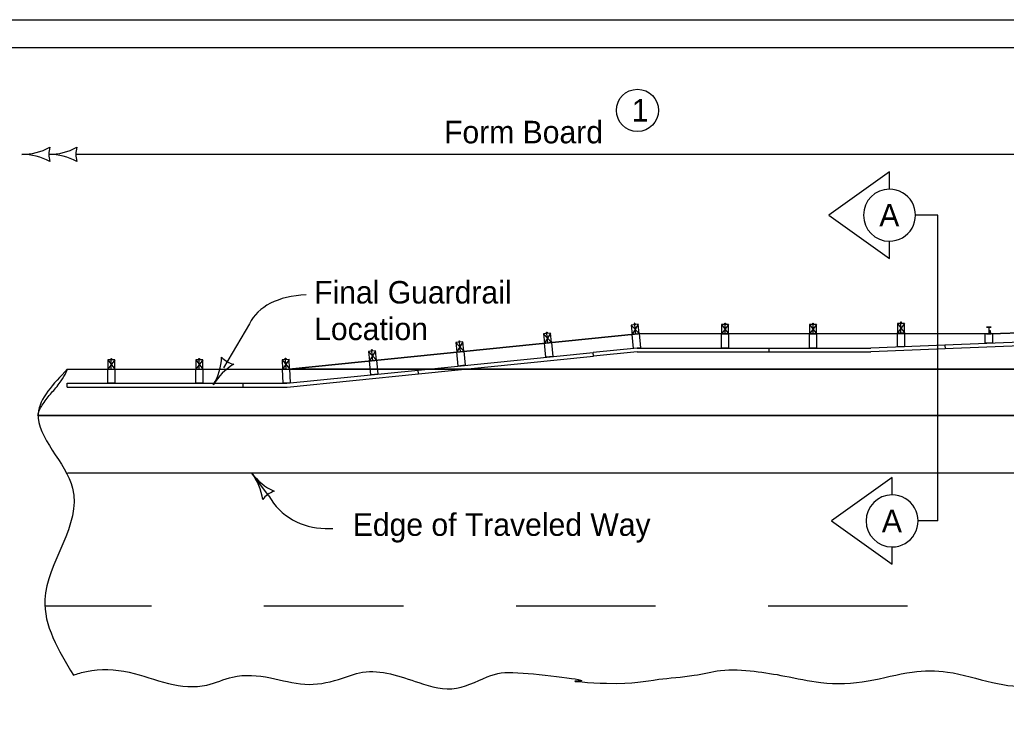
# Model space of a CAD drawing. Extents: x 8045 to 81668, y 6217 to 16762.
# Drawn here: x 10335 to 11036, y 9440 to 9944 of the extents above; entities that cross this region are included whole.
import ezdxf

# ---------------------------------------------------------------- set-up
doc = ezdxf.new("R2010")
doc.units = 0
for name, color, linetype in [('dsnCellElements', 7, 'Continuous'), ('dsnStdDetailExtension', 7, 'Continuous'), ('dsnStdDimension', 7, 'Continuous'), ('dsnStdLabel', 7, 'Continuous'), ('dsnStdNote', 7, 'Continuous'), ('dsnStdPattern', 7, 'Continuous'), ('dsnStdSection', 7, 'Continuous'), ('Level 4', 7, 'Continuous'), ('Level 8', 7, 'Continuous')]:
    doc.layers.add(name, color=color, linetype=linetype)

msp = doc.modelspace()

# ---------------------------------------------------------------- linework, layer by layer
at = {"layer": 'dsnCellElements'}
msp.add_line((10375.45, 9848.49), (11397.86, 9848.49), dxfattribs=at)
msp.add_line((10375.45, 9848.49), (11397.86, 9848.49), dxfattribs=at)
for centre, radius, start, end in [((10336.23, 9890.84), 42.5, 270, 298.07249), ((10336.23, 9890.84), 42.5, 270, 298.07249), ((10355.45, 9890.84), 42.5, 270, 298.07249), ((10371.87, 9848.34), 16.42, 162.26665, 197.73335), ((10355.45, 9890.84), 42.5, 270, 298.07249), ((10371.87, 9848.34), 16.42, 162.26665, 197.73335), ((10391.09, 9848.34), 16.42, 162.26665, 197.73335), ((10391.09, 9848.34), 16.42, 162.26665, 197.73335), ((10336.23, 9805.84), 42.5, 61.92751, 90), ((10336.23, 9805.84), 42.5, 61.92751, 90), ((10355.45, 9805.84), 42.5, 61.92751, 90), ((10355.45, 9805.84), 42.5, 61.92751, 90)]:
    msp.add_arc(centre, radius, start, end, dxfattribs=at)
at = {"layer": 'dsnStdDetailExtension'}
for p, q in [((10769.49, 9727.04), (10775.13, 9720.91)), ((10774.47, 9727.54), (10770.15, 9720.41)), ((10771.88, 9728.26), (10771.87, 9728.33)), ((10772.64, 9720.66), (10771.98, 9727.29)), ((10833.64, 9727.37), (10838.64, 9720.71)), ((10838.64, 9727.37), (10833.64, 9720.71)), ((10836.14, 9728.35), (10836.14, 9728.42)), ((10836.14, 9720.71), (10836.14, 9727.37)), ((10896.14, 9727.37), (10901.14, 9720.71)), ((10901.14, 9727.37), (10896.14, 9720.71)), ((10898.64, 9728.35), (10898.64, 9728.42)), ((10898.64, 9720.71), (10898.64, 9727.37)), ((10958.64, 9728.24), (10963.64, 9721.57)), ((10963.64, 9728.24), (10958.64, 9721.57)), ((10961.14, 9729.21), (10961.14, 9729.28)), ((10961.14, 9721.57), (10961.14, 9728.24)), ((10707.03, 9720.76), (10712.67, 9714.63)), ((10712, 9721.26), (10707.69, 9714.13)), ((10709.42, 9721.98), (10709.41, 9722.05)), ((10710.18, 9714.38), (10709.51, 9721.01)), ((10770.15, 9720.41), (10775.13, 9720.91)), ((10772.64, 9720.66), (10770.15, 9720.41)), ((10772.64, 9720.66), (10770.15, 9720.41)), ((10771.15, 9710.45), (10770.15, 9720.41)), ((10775.13, 9720.91), (10776.13, 9710.95)), ((10833.64, 9720.71), (10838.64, 9720.71)), ((10833.64, 9710.7), (10833.64, 9720.71)), ((10838.64, 9720.71), (10838.64, 9710.7)), ((10896.14, 9720.71), (10901.14, 9720.71)), ((10896.14, 9710.7), (10896.14, 9720.71)), ((10901.14, 9720.71), (10901.14, 9710.7)), ((10958.64, 9721.57), (10963.64, 9721.57)), ((10958.64, 9711.56), (10958.64, 9721.57)), ((10963.64, 9721.57), (10963.64, 9711.56)), ((10644.84, 9714.51), (10650.48, 9708.38)), ((10649.81, 9715.01), (10645.51, 9707.88)), ((10647.23, 9715.73), (10647.22, 9715.8)), ((10647.99, 9708.13), (10647.33, 9714.76)), ((10707.69, 9714.13), (10712.67, 9714.63)), ((10708.69, 9704.17), (10707.69, 9714.13)), ((10712.67, 9714.63), (10713.67, 9704.67)), ((10963.64, 9711.56), (10958.64, 9711.56)), ((10582.66, 9708.3), (10588.3, 9702.13)), ((10587.64, 9708.8), (10583.33, 9701.63)), ((10585.05, 9709.52), (10585.05, 9709.59)), ((10585.81, 9701.88), (10585.15, 9708.55)), ((10617.9, 9695.05), (10742.28, 9707.55)), ((10618.17, 9692.35), (10742.55, 9704.85)), ((10645.51, 9707.88), (10650.49, 9708.38)), ((10646.51, 9697.92), (10645.51, 9707.88)), ((10650.49, 9708.38), (10651.49, 9698.42)), ((10713.67, 9704.67), (10708.69, 9704.17)), ((10773.64, 9710.7), (10742.28, 9707.55)), ((10742.55, 9704.85), (10742.28, 9707.55)), ((10742.55, 9704.87), (10742.28, 9707.55)), ((10773.64, 9707.99), (10742.55, 9704.87)), ((10776.13, 9710.95), (10771.15, 9710.45)), ((10773.64, 9710.7), (10867.39, 9710.7)), ((10773.64, 9707.99), (10867.39, 9707.99)), ((10838.64, 9710.7), (10833.64, 9710.7)), ((10867.39, 9707.99), (10867.39, 9710.7)), ((10867.39, 9710.7), (10939.63, 9710.7)), ((10867.39, 9707.99), (10867.39, 9710.7)), ((10867.39, 9707.99), (10939.65, 9707.99)), ((10901.14, 9710.7), (10896.14, 9710.7)), ((10397.39, 9702.3), (10402.39, 9695.63)), ((10402.39, 9702.3), (10397.39, 9695.63)), ((10399.89, 9703.27), (10399.89, 9703.34)), ((10399.89, 9695.63), (10399.89, 9702.3)), ((10459.89, 9702.3), (10464.89, 9695.63)), ((10464.89, 9702.3), (10459.89, 9695.63)), ((10462.39, 9703.27), (10462.39, 9703.34)), ((10462.39, 9695.63), (10462.39, 9702.3)), ((10521.28, 9702.36), (10526.61, 9695.92)), ((10526.28, 9702.61), (10521.62, 9695.67)), ((10523.73, 9703.46), (10523.73, 9703.53)), ((10524.11, 9695.8), (10523.78, 9702.49)), ((10583.33, 9701.63), (10588.3, 9702.13)), ((10584.32, 9691.63), (10583.33, 9701.63)), ((10588.3, 9702.13), (10589.3, 9692.13)), ((10651.49, 9698.42), (10646.51, 9697.92)), ((10397.39, 9695.63), (10402.4, 9695.63)), ((10397.39, 9685.63), (10397.39, 9695.63)), ((10402.4, 9695.63), (10402.4, 9685.63)), ((10459.89, 9695.63), (10464.9, 9695.63)), ((10459.89, 9685.63), (10459.89, 9695.63)), ((10464.9, 9695.63), (10464.9, 9685.63)), ((10521.62, 9695.67), (10526.61, 9695.92)), ((10522.11, 9685.63), (10521.62, 9695.67)), ((10524.62, 9685.63), (10617.9, 9695.05)), ((10524.89, 9682.92), (10618.17, 9692.34)), ((10526.61, 9695.92), (10527.11, 9685.88)), ((10589.3, 9692.13), (10584.32, 9691.63)), ((10618.17, 9692.34), (10617.9, 9695.05)), ((10618.17, 9692.35), (10617.9, 9695.05)), ((10368.64, 9685.63), (10493.64, 9685.63)), ((10368.64, 9682.92), (10368.64, 9685.63)), ((10402.4, 9685.63), (10397.39, 9685.63)), ((10464.9, 9685.63), (10459.89, 9685.63)), ((10493.64, 9685.63), (10524.62, 9685.63)), ((10493.64, 9682.92), (10493.64, 9685.63)), ((10527.11, 9685.88), (10522.11, 9685.63)), ((10368.64, 9682.92), (10493.64, 9682.92)), ((10493.64, 9682.92), (10524.89, 9682.92))]:
    msp.add_line(p, q, dxfattribs=at)
for points in [[(10770.15, 9720.41), (10775.13, 9720.91), (10774.47, 9727.54), (10769.49, 9727.04)], [(10833.64, 9720.71), (10838.64, 9720.71), (10838.64, 9727.37), (10833.64, 9727.37)], [(10896.14, 9720.71), (10901.14, 9720.71), (10901.14, 9727.37), (10896.14, 9727.37)], [(10958.64, 9721.57), (10963.64, 9721.57), (10963.64, 9728.24), (10958.64, 9728.24)], [(10707.69, 9714.13), (10712.67, 9714.63), (10712, 9721.26), (10707.03, 9720.76)], [(10645.51, 9707.88), (10650.48, 9708.38), (10649.81, 9715.01), (10644.84, 9714.51)], [(10583.33, 9701.63), (10588.3, 9702.13), (10587.64, 9708.8), (10582.66, 9708.3)], [(10397.39, 9695.63), (10402.39, 9695.63), (10402.39, 9702.3), (10397.39, 9702.3)], [(10459.89, 9695.63), (10464.89, 9695.63), (10464.89, 9702.3), (10459.89, 9702.3)], [(10521.62, 9695.67), (10526.61, 9695.92), (10526.28, 9702.61), (10521.28, 9702.36)]]:
    msp.add_lwpolyline(points, close=True, dxfattribs=at)
for points in [[(10771.65, 9727.26), (10771.6, 9727.69), (10772.27, 9727.75), (10772.31, 9727.32)], [(10771.74, 9727.7), (10771.69, 9728.24), (10772.08, 9728.28), (10772.13, 9727.74)], [(10835.8, 9727.37), (10835.8, 9727.81), (10836.47, 9727.81), (10836.47, 9727.37)], [(10835.94, 9727.81), (10835.94, 9728.35), (10836.33, 9728.35), (10836.33, 9727.81)], [(10898.31, 9727.37), (10898.31, 9727.81), (10898.97, 9727.81), (10898.97, 9727.37)], [(10898.45, 9727.81), (10898.45, 9728.35), (10898.83, 9728.35), (10898.83, 9727.81)], [(10960.81, 9728.24), (10960.81, 9728.67), (10961.47, 9728.67), (10961.47, 9728.24)], [(10960.95, 9728.67), (10960.95, 9729.21), (10961.33, 9729.21), (10961.33, 9728.67)], [(10709.18, 9720.98), (10709.14, 9721.41), (10709.8, 9721.48), (10709.85, 9721.05)], [(10709.28, 9721.42), (10709.22, 9721.96), (10709.61, 9722), (10709.66, 9721.46)], [(10647, 9714.73), (10646.95, 9715.16), (10647.62, 9715.23), (10647.66, 9714.8)], [(10647.09, 9715.17), (10647.04, 9715.71), (10647.42, 9715.75), (10647.48, 9715.21)], [(10584.82, 9708.52), (10584.78, 9708.95), (10585.44, 9709.01), (10585.48, 9708.58)], [(10584.91, 9708.96), (10584.86, 9709.5), (10585.25, 9709.54), (10585.3, 9709)], [(10399.56, 9702.3), (10399.56, 9702.73), (10400.23, 9702.73), (10400.23, 9702.3)], [(10399.7, 9702.73), (10399.7, 9703.27), (10400.09, 9703.27), (10400.09, 9702.73)], [(10462.06, 9702.3), (10462.06, 9702.73), (10462.73, 9702.73), (10462.73, 9702.3)], [(10462.2, 9702.73), (10462.2, 9703.27), (10462.59, 9703.27), (10462.59, 9702.73)], [(10523.45, 9702.47), (10523.43, 9702.9), (10524.09, 9702.94), (10524.11, 9702.51)], [(10523.57, 9702.91), (10523.54, 9703.45), (10523.93, 9703.47), (10523.95, 9702.93)], [(10524.11, 9695.8), (10521.62, 9695.67), (10521.62, 9695.67)]]:
    msp.add_lwpolyline(points, dxfattribs=at)
at = {"layer": 'dsnStdDimension'}
msp.add_line((10152.18, 9924.36), (13247.87, 9924.36), dxfattribs=at)
at = {"layer": 'dsnStdLabel'}
for p, q in [((11025.35, 9720.71), (11500.75, 9740.23)), ((11403.96, 9729.27), (10992.39, 9712.81)), ((11404.06, 9726.57), (10992.39, 9710.1)), ((11022.02, 9725.6), (11022.02, 9725.45)), ((11025.35, 9725.6), (11022.02, 9725.6)), ((11022.02, 9725.45), (11023.19, 9725.45)), ((11024.18, 9725.45), (11025.35, 9725.45)), ((11025.35, 9725.45), (11025.35, 9725.6)), ((10526.39, 9695.63), (10774.18, 9720.71)), ((11022.02, 9720.71), (10774.18, 9720.71)), ((11021.08, 9714.06), (11021.08, 9721.02)), ((11021.08, 9721.02), (11021.71, 9721.02)), ((11021.71, 9720.71), (11021.71, 9721.02)), ((11025.46, 9720.71), (11021.71, 9720.71)), ((11022.02, 9720.86), (11022.02, 9720.71)), ((11023.19, 9720.86), (11022.02, 9720.86)), ((11022.02, 9720.71), (11025.35, 9720.71)), ((11023.61, 9725.03), (11023.61, 9721.28)), ((11023.77, 9721.28), (11023.77, 9725.03)), ((11024, 9721.39), (11023.92, 9721.33)), ((11023.92, 9720.96), (11023.92, 9721.33)), ((11024, 9721.39), (11024.97, 9721.39)), ((11025.35, 9720.86), (11024.18, 9720.86)), ((11024.22, 9720.92), (11024.22, 9721.33)), ((11024.78, 9722.9), (11024.26, 9722.9)), ((11024.26, 9722.9), (11024.26, 9721.39)), ((11024.78, 9721.39), (11024.78, 9722.9)), ((11024.82, 9720.92), (11024.82, 9721.33)), ((11024.97, 9721.39), (11025.04, 9721.39)), ((11025.12, 9721.33), (11025.04, 9721.39)), ((11025.04, 9720.86), (11025.12, 9720.92)), ((11025.12, 9720.92), (11025.12, 9721.33)), ((11025.35, 9720.71), (11025.35, 9720.86)), ((11025.46, 9721.02), (11026.08, 9721.02)), ((11025.46, 9721.02), (11025.46, 9720.71)), ((11026.08, 9721.02), (11026.08, 9714.06)), ((10992.39, 9712.81), (10939.63, 9710.7)), ((10992.39, 9712.81), (10992.5, 9710.11)), ((10992.39, 9712.81), (10992.5, 9710.11)), ((11026.08, 9714.06), (11021.08, 9714.06)), ((10992.5, 9710.11), (10939.65, 9707.99)), ((10368.64, 9695.63), (10526.39, 9695.63)), ((10368.64, 9695.63), (11500.75, 9695.63)), ((10347.65, 9662.65), (11995.12, 9662.65)), ((11500.75, 9662.65), (10347.65, 9662.65)), ((10368.86, 9622), (11982.65, 9622)), ((10353.42, 9527.54), (10428.38, 9527.54)), ((10508.38, 9527.54), (10607.54, 9527.54)), ((10687.54, 9527.54), (10786.71, 9527.54)), ((10866.71, 9527.54), (10965.88, 9527.54))]:
    msp.add_line(p, q, dxfattribs=at)
for centre, start, end in [((11023.19, 9725.03), 359.99336, 90.00253), ((11024.18, 9725.03), 90.00734, 179.99635), ((11023.19, 9721.28), 270.00734, 359.99635), ((11024.18, 9721.28), 264.71743, 270.00253)]:
    msp.add_arc(centre, 0.417, start, end, dxfattribs=at)
for points in [[(11024.22, 9721.33), (11024.2, 9721.35), (11024.15, 9721.38), (11024.06, 9721.39), (11023.99, 9721.37), (11023.94, 9721.35), (11023.92, 9721.33)], [(11024.12, 9720.87), (11024.13, 9720.88), (11024.17, 9720.88), (11024.2, 9720.9), (11024.22, 9720.92)], [(11024.82, 9721.33), (11024.77, 9721.35), (11024.66, 9721.38), (11024.51, 9721.39), (11024.36, 9721.37), (11024.27, 9721.35), (11024.22, 9721.33)], [(11024.22, 9720.92), (11024.27, 9720.9), (11024.38, 9720.87), (11024.54, 9720.86), (11024.69, 9720.88), (11024.78, 9720.9), (11024.82, 9720.92)], [(11025.12, 9721.33), (11025.11, 9721.34), (11025.07, 9721.36), (11025.01, 9721.38), (11024.94, 9721.39), (11024.87, 9721.36), (11024.83, 9721.34), (11024.82, 9721.33)], [(11024.82, 9720.92), (11024.83, 9720.91), (11024.87, 9720.89), (11024.94, 9720.86), (11025.01, 9720.87), (11025.07, 9720.89), (11025.11, 9720.91), (11025.12, 9720.92)]]:
    msp.add_open_spline(points, degree=3, dxfattribs=at)
for points in [[(10368.64, 9695.63), (10347.99, 9664.08), (10372.36, 9611), (10352.66, 9531.9), (10372.93, 9478.29)], [(10347.65, 9662.65), (10347.99, 9664.08), (10349.68, 9668.15), (10352.09, 9672.07), (10358.15, 9679.69), (10364.3, 9687.38), (10367.83, 9693.49), (10368.64, 9695.63)], [(10372.93, 9478.29), (10382.36, 9480.86), (10412.58, 9480.29), (10440.52, 9472.31), (10467.89, 9471.16), (10486.14, 9476.87), (10512.94, 9476.3), (10537.46, 9471.74), (10561.41, 9475.16), (10578.52, 9480.29), (10618.43, 9472.88), (10645.23, 9468.88), (10669.75, 9478.01), (10692.56, 9479.72), (10731.34, 9474.02), (10730.77, 9474.02), (10751.92, 9472.41), (10788.99, 9475.27), (10814.08, 9478.12), (10832.9, 9481.54), (10856.85, 9480.97), (10878.51, 9477.55), (10904.17, 9472.98), (10937.82, 9474.13), (10969.18, 9480.4), (10994.27, 9480.4), (11026.2, 9472.98), (11055.29, 9470.13), (11088.93, 9476.98), (11121.43, 9480.4), (11155.65, 9473.55), (11181.31, 9470.7), (11203.54, 9474.13), (11231.49, 9489.53), (11241.75, 9491.81), (11266.27, 9494.09), (11296.93, 9494.66), (11318.03, 9494.66), (11371.34, 9485.38)]]:
    msp.add_spline(points, degree=3, dxfattribs=at)
at = {"layer": 'dsnStdNote'}
for p, q in [((10498.16, 9728.01), (10479.61, 9696.66)), ((10498.16, 9728.01), (10479.61, 9696.66)), ((10511.77, 9605.55), (10499.66, 9622)), ((10511.77, 9605.55), (10499.66, 9622)), ((10551.86, 9582.48), (10557.31, 9582.48)), ((10551.86, 9582.48), (10557.31, 9582.48))]:
    msp.add_line(p, q, dxfattribs=at)
for centre, radius, start, end in [((10435.84, 9706.16), 42.5, 329.37973, 357.45222), ((10435.84, 9706.16), 42.5, 329.37973, 357.45222), ((10490.57, 9715.18), 16.42, 221.64638, 257.11308), ((10490.57, 9715.18), 16.42, 221.64638, 257.11308), ((10508.99, 9662.87), 42.5, 121.30724, 149.37973), ((10508.99, 9662.87), 42.5, 121.30724, 149.37973), ((10533.88, 9647.21), 42.5, 216.37256, 244.44505), ((10465.44, 9596.8), 42.5, 8.30007, 36.37256), ((10533.88, 9647.21), 42.5, 216.37256, 244.44505), ((10465.44, 9596.8), 42.5, 8.30007, 36.37256), ((10520.79, 9593.31), 16.42, 108.63921, 144.10591), ((10520.79, 9593.31), 16.42, 108.63921, 144.10591), ((10551.92, 9628.94), 46.46, 210.22743, 270), ((10551.92, 9628.94), 46.46, 210.22743, 270)]:
    msp.add_arc(centre, radius, start, end, dxfattribs=at)
msp.add_ellipse((10579.25, 9688.96), major_axis=(-81.09, 39.04), ratio=0.555556, start_param=5.482641, end_param=6.283185, dxfattribs=at)
msp.add_ellipse((10579.25, 9688.96), major_axis=(-81.09, 39.04), ratio=0.555556, start_param=5.482641, end_param=6.283185, dxfattribs=at)
at = {"layer": 'dsnStdPattern'}
for p, q in [((11025.35, 9725.6), (11022.02, 9725.6)), ((11022.02, 9725.6), (11022.02, 9725.45)), ((11022.02, 9725.6), (11022.02, 9725.45)), ((11025.35, 9725.6), (11022.02, 9725.6)), ((11022.02, 9725.45), (11023.19, 9725.45)), ((11022.02, 9725.45), (11023.19, 9725.45)), ((11024.18, 9725.45), (11025.35, 9725.45)), ((11024.18, 9725.45), (11025.35, 9725.45)), ((11025.35, 9725.45), (11025.35, 9725.6)), ((11025.35, 9725.45), (11025.35, 9725.6)), ((11021.08, 9714.06), (11021.08, 9721.02)), ((11021.08, 9721.02), (11021.71, 9721.02)), ((11021.71, 9720.71), (11021.71, 9721.02)), ((11025.46, 9720.71), (11021.71, 9720.71)), ((11023.19, 9720.86), (11022.02, 9720.86)), ((11022.02, 9720.86), (11022.02, 9720.71)), ((11022.02, 9720.86), (11022.02, 9720.71)), ((11023.19, 9720.86), (11022.02, 9720.86)), ((11022.02, 9720.71), (11025.35, 9720.71)), ((11022.02, 9720.71), (11025.35, 9720.71)), ((11023.61, 9725.03), (11023.61, 9721.28)), ((11023.61, 9725.03), (11023.61, 9721.28)), ((11023.77, 9721.28), (11023.77, 9725.03)), ((11023.77, 9721.28), (11023.77, 9725.03)), ((11024, 9721.39), (11023.92, 9721.33)), ((11024, 9721.39), (11023.92, 9721.33)), ((11023.92, 9721.33), (11023.92, 9720.96)), ((11023.92, 9720.96), (11023.92, 9721.33)), ((11024, 9721.39), (11024.97, 9721.39)), ((11024.97, 9721.39), (11024, 9721.39)), ((11025.35, 9720.86), (11024.18, 9720.86)), ((11025.35, 9720.86), (11024.18, 9720.86)), ((11024.22, 9721.33), (11024.22, 9720.92)), ((11024.22, 9720.92), (11024.22, 9721.33)), ((11024.22, 9720.92), (11024.22, 9721.33)), ((11024.78, 9722.9), (11024.26, 9722.9)), ((11024.26, 9722.9), (11024.26, 9721.39)), ((11024.78, 9722.9), (11024.26, 9722.9)), ((11024.26, 9722.9), (11024.26, 9721.39)), ((11024.26, 9721.39), (11024.78, 9721.39)), ((11024.78, 9721.39), (11024.78, 9722.9)), ((11024.78, 9721.39), (11024.78, 9722.9)), ((11024.82, 9720.92), (11024.82, 9721.33)), ((11024.82, 9721.33), (11024.82, 9720.92)), ((11024.82, 9720.92), (11024.82, 9721.33)), ((11024.97, 9721.39), (11025.04, 9721.39)), ((11025.04, 9721.39), (11024.97, 9721.39)), ((11025.12, 9721.33), (11025.04, 9721.39)), ((11025.12, 9721.33), (11025.04, 9721.39)), ((11025.04, 9720.86), (11025.12, 9720.92)), ((11025.04, 9720.86), (11025.12, 9720.92)), ((11025.12, 9720.92), (11025.12, 9721.33)), ((11025.12, 9720.92), (11025.12, 9721.33)), ((11025.35, 9720.71), (11025.35, 9720.86)), ((11025.35, 9720.71), (11025.35, 9720.86)), ((11025.46, 9721.02), (11026.08, 9721.02)), ((11025.46, 9721.02), (11025.46, 9720.71)), ((11026.08, 9721.02), (11026.08, 9714.06)), ((11026.08, 9714.06), (11021.08, 9714.06))]:
    msp.add_line(p, q, dxfattribs=at)
for points in [[(11023.92, 9720.96), (11023.92, 9720.96)], [(11024.18, 9720.86), (11025.04, 9720.86), (11025.04, 9720.86)]]:
    msp.add_lwpolyline(points, dxfattribs=at)
for centre, start, end in [((11023.19, 9725.03), 359.99336, 90.00253), ((11023.19, 9725.03), 359.99336, 90.00253), ((11024.18, 9725.03), 90.00734, 179.99635), ((11024.18, 9725.03), 90.00734, 179.99635), ((11023.19, 9721.28), 270.00734, 359.99635), ((11023.19, 9721.28), 270.00734, 359.99635), ((11024.18, 9721.28), 179.99336, 270.00253), ((11024.18, 9721.28), 179.99336, 270.00253), ((11024.18, 9721.28), 230.88662, 270.00253)]:
    msp.add_arc(centre, 0.417, start, end, dxfattribs=at)
for points in [[(11024.22, 9721.33), (11024.2, 9721.35), (11024.15, 9721.38), (11024.06, 9721.39), (11023.99, 9721.37), (11023.94, 9721.35), (11023.92, 9721.33)], [(11024.22, 9721.33), (11024.2, 9721.35), (11024.15, 9721.38), (11024.06, 9721.39), (11023.99, 9721.37), (11023.94, 9721.35), (11023.92, 9721.33)], [(11023.92, 9721.33), (11023.94, 9721.35), (11023.99, 9721.37), (11024.06, 9721.39), (11024.15, 9721.38), (11024.2, 9721.35), (11024.22, 9721.33)], [(11024.12, 9720.87), (11024.13, 9720.88), (11024.17, 9720.88), (11024.2, 9720.9), (11024.22, 9720.92)], [(11024.82, 9721.33), (11024.77, 9721.35), (11024.66, 9721.38), (11024.51, 9721.39), (11024.36, 9721.37), (11024.27, 9721.35), (11024.22, 9721.33)], [(11024.82, 9721.33), (11024.77, 9721.35), (11024.66, 9721.38), (11024.51, 9721.39), (11024.36, 9721.37), (11024.27, 9721.35), (11024.22, 9721.33)], [(11024.22, 9721.33), (11024.27, 9721.35), (11024.36, 9721.37), (11024.51, 9721.39), (11024.66, 9721.38), (11024.77, 9721.35), (11024.82, 9721.33)], [(11024.22, 9720.92), (11024.27, 9720.9), (11024.38, 9720.87), (11024.54, 9720.86), (11024.69, 9720.88), (11024.78, 9720.9), (11024.82, 9720.92)], [(11024.82, 9720.92), (11024.78, 9720.9), (11024.69, 9720.88), (11024.54, 9720.86), (11024.38, 9720.87), (11024.27, 9720.9), (11024.22, 9720.92)], [(11024.22, 9720.92), (11024.27, 9720.9), (11024.38, 9720.87), (11024.54, 9720.86), (11024.69, 9720.88), (11024.78, 9720.9), (11024.82, 9720.92)], [(11025.12, 9721.33), (11025.11, 9721.34), (11025.07, 9721.36), (11025.01, 9721.38), (11024.94, 9721.39), (11024.87, 9721.36), (11024.83, 9721.34), (11024.82, 9721.33)], [(11025.12, 9721.33), (11025.11, 9721.34), (11025.07, 9721.36), (11025.01, 9721.38), (11024.94, 9721.39), (11024.87, 9721.36), (11024.83, 9721.34), (11024.82, 9721.33)], [(11024.82, 9721.33), (11024.83, 9721.34), (11024.87, 9721.36), (11024.94, 9721.39), (11025.01, 9721.38), (11025.07, 9721.36), (11025.11, 9721.34), (11025.12, 9721.33)], [(11024.82, 9720.92), (11024.83, 9720.91), (11024.87, 9720.89), (11024.94, 9720.86), (11025.01, 9720.87), (11025.07, 9720.89), (11025.11, 9720.91), (11025.12, 9720.92)], [(11025.12, 9720.92), (11025.11, 9720.91), (11025.07, 9720.89), (11025.01, 9720.87), (11024.94, 9720.86), (11024.87, 9720.89), (11024.83, 9720.91), (11024.82, 9720.92)], [(11024.82, 9720.92), (11024.83, 9720.91), (11024.87, 9720.89), (11024.94, 9720.86), (11025.01, 9720.87), (11025.07, 9720.89), (11025.11, 9720.91), (11025.12, 9720.92)]]:
    msp.add_open_spline(points, degree=3, dxfattribs=at)
at = {"layer": 'dsnStdSection'}
msp.add_lwpolyline([(10132.52, 9944.02), (13267.53, 9944.02), (13267.53, 7924.02), (10132.52, 7924.02)], close=True, dxfattribs=at)
at = {"layer": 'Level 4'}
for p, q in [((10987.26, 9805.1), (10971.49, 9805.1)), ((10987.26, 9805.1), (10971.49, 9805.1)), ((10987.26, 9587.81), (10987.26, 9805.1)), ((10987.26, 9587.81), (10987.26, 9805.1)), ((11454.21, 9738.32), (11025.35, 9720.71)), ((10774.18, 9720.71), (10526.39, 9695.63)), ((11025.35, 9720.71), (10774.18, 9720.71)), ((10526.39, 9695.63), (11500.75, 9695.63)), ((11558.3, 9695.63), (10526.39, 9695.63)), ((10987.26, 9587.81), (10973.31, 9587.81)), ((10987.26, 9587.81), (10973.31, 9587.81))]:
    msp.add_line(p, q, dxfattribs=at)
for points in [[(10953, 9823.58), (10953, 9835.91), (10909.87, 9805.1), (10953, 9774.29), (10953, 9786.61)], [(10954.82, 9606.3), (10954.82, 9618.62), (10911.69, 9587.81), (10954.82, 9557), (10954.82, 9569.33)]]:
    msp.add_lwpolyline(points, dxfattribs=at)
for centre, start, end in [((10953, 9805.1), 90.00083, 269.99917), ((10953, 9805.1), 269.99917, 90.00083), ((10954.82, 9587.81), 90.00083, 269.99917), ((10954.82, 9587.81), 269.99917, 90.00083)]:
    msp.add_arc(centre, 18.49, start, end, dxfattribs=at)
at = {"layer": 'Level 8'}
msp.add_circle((10773.85, 9879.62), 15, dxfattribs=at)

# ---------------------------------------------------------------- texts
at = {"layer": 'dsnCellElements'}
msp.add_text('Form Board', height=16, dxfattribs=at).set_placement((10636.4, 9856.18))
msp.add_text('Form Board', height=16, dxfattribs=at).set_placement((10636.4, 9856.18))
at = {"layer": 'dsnStdNote'}
for s, p in [('Final Guardrail ', (10544.06, 9742.33)), ('Final Guardrail ', (10544.06, 9742.33)), ('Location', (10544.06, 9716.33)), ('Location', (10544.06, 9716.33)), ('Edge of Traveled Way', (10571.5, 9577.21)), ('Edge of Traveled Way', (10571.5, 9577.21))]:
    msp.add_text(s, height=16, dxfattribs=at).set_placement(p)
at = {"layer": 'Level 4'}
for p in [(10945.73, 9797.1), (10947.55, 9579.81)]:
    msp.add_text('A', height=16, dxfattribs=at).set_placement(p)
at = {"layer": 'Level 8'}
msp.add_text('1', height=16, dxfattribs=at).set_placement((10769.77, 9871.62))

doc.saveas('drawing.dxf')
